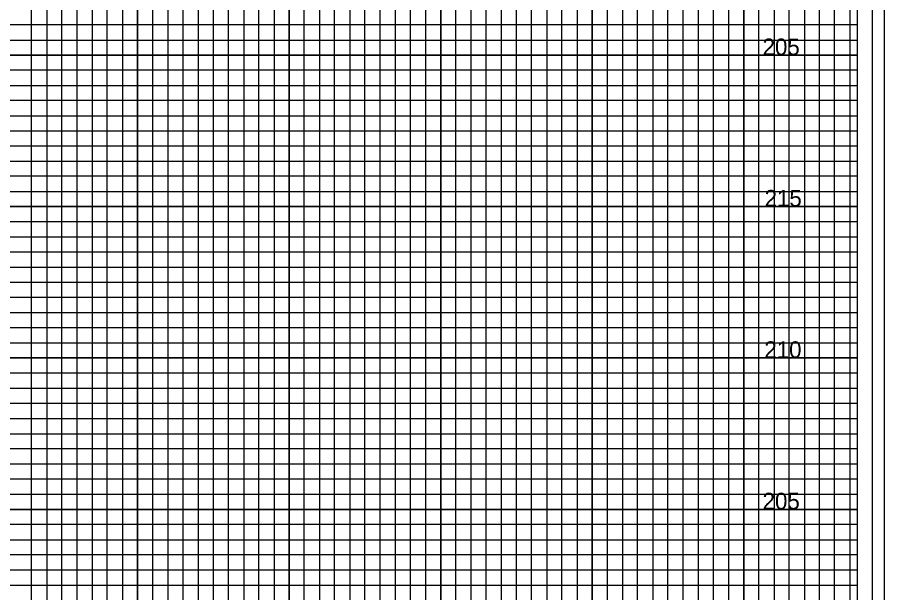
# Model space of a CAD drawing. Extents: x -4 to 103, y -2 to 209.
# Drawn here: x 74.78 to 103.4, y 32.25 to 51.25 of the extents above; entities that cross this region are included whole.
import ezdxf

# ---------------------------------------------------------------- set-up
doc = ezdxf.new("R2010")
doc.units = 0
for name, color, linetype in [('Old_Level_10', 7, 'Continuous'), ('Old_Level_17', 7, 'Continuous'), ('Old_Level_5', 7, 'Continuous'), ('Old_Level_6', 7, 'Continuous'), ('Old_Level_8', 7, 'Continuous'), ('Prop Dimension', 7, 'Continuous'), ('Typical Curb CELL', 7, 'Continuous')]:
    doc.layers.add(name, color=color, linetype=linetype)

msp = doc.modelspace()

# ---------------------------------------------------------------- linework, layer by layer
at = {"layer": 'Old_Level_10'}
for p, q in [((91.25, 0), (91.25, 63.425)), ((93.75, 0), (93.75, 63.425)), ((96.25, 0), (96.25, 63.425)), ((98.75, 0), (98.75, 63.425)), ((101.25, 0), (101.25, 63.425)), ((76.25, 0), (76.25, 62)), ((78.75, 0), (78.75, 62)), ((81.25, 0), (81.25, 62)), ((83.75, 0), (83.75, 62)), ((86.25, 0), (86.25, 62)), ((88.75, 0), (88.75, 62)), ((0, 50), (102.5, 50)), ((0, 47.5), (102.5, 47.5)), ((0, 45), (102.5, 45)), ((0, 42.5), (102.5, 42.5)), ((0, 40), (102.5, 40)), ((0, 37.5), (102.5, 37.5)), ((0, 35), (102.5, 35)), ((0, 32.5), (102.5, 32.5))]:
    msp.add_line(p, q, dxfattribs=at)
at = {"layer": 'Old_Level_17'}
for points in [[(90.25, 0), (90.25, 63.425), (90.75, 63.425), (90.75, 0)], [(91.75, 0), (91.75, 63.425), (92.25, 63.425), (92.25, 0)], [(92.75, 0), (92.75, 63.425), (93.25, 63.425), (93.25, 0)], [(94.25, 0), (94.25, 63.425), (94.75, 63.425), (94.75, 0)], [(95.25, 0), (95.25, 63.425), (95.75, 63.425), (95.75, 0)], [(96.75, 0), (96.75, 63.425), (97.25, 63.425), (97.25, 0)], [(97.75, 0), (97.75, 63.425), (98.25, 63.425), (98.25, 0)], [(99.25, 0), (99.25, 63.425), (99.75, 63.425), (99.75, 0)], [(100.25, 0), (100.25, 63.425)], [(100.25, 63.425), (100.75, 63.425), (100.75, 0), (101.75, 0), (101.75, 63.425), (102.25, 63.425), (102.25, 0)], [(75.25, 0), (75.25, 62), (75.75, 62), (75.75, 0)], [(76.75, 0), (76.75, 62), (77.25, 62), (77.25, 0)], [(77.75, 0), (77.75, 62), (78.25, 62), (78.25, 0)], [(79.25, 0), (79.25, 62), (79.75, 62), (79.75, 0)], [(80.25, 0), (80.25, 62), (80.75, 62), (80.75, 0)], [(81.75, 0), (81.75, 62), (82.25, 62), (82.25, 0)], [(82.75, 0), (82.75, 62), (83.25, 62), (83.25, 0)], [(84.25, 0), (84.25, 62), (84.75, 62), (84.75, 0)], [(85.25, 0), (85.25, 62), (85.75, 62), (85.75, 0)], [(86.75, 0), (86.75, 62), (87.25, 62), (87.25, 0)], [(87.75, 0), (87.75, 62), (88.25, 62), (88.25, 0)], [(89.25, 0), (89.25, 62), (89.75, 62), (89.75, 0)], [(0, 50.5), (102.5, 50.5), (102.5, 51), (0, 51)], [(0, 49), (102.5, 49), (102.5, 49.5), (0, 49.5)], [(0, 48), (102.5, 48), (102.5, 48.5), (0, 48.5)], [(0, 46.5), (102.5, 46.5), (102.5, 47), (0, 47)], [(0, 45.5), (102.5, 45.5), (102.5, 46), (0, 46)], [(0, 44), (102.5, 44), (102.5, 44.5), (0, 44.5)], [(0, 43), (102.5, 43), (102.5, 43.5), (0, 43.5)], [(0, 41.5), (102.5, 41.5), (102.5, 42), (0, 42)], [(0, 40.5), (102.5, 40.5), (102.5, 41), (0, 41)], [(0, 39), (102.5, 39), (102.5, 39.5), (0, 39.5)], [(0, 38), (102.5, 38), (102.5, 38.5), (0, 38.5)], [(0, 36.5), (102.5, 36.5), (102.5, 37), (0, 37)], [(0, 35.5), (102.5, 35.5), (102.5, 36), (0, 36)], [(0, 34), (102.5, 34), (102.5, 34.5), (0, 34.5)], [(0, 33), (102.5, 33), (102.5, 33.5), (0, 33.5)]]:
    msp.add_lwpolyline(points, dxfattribs=at)
at = {"layer": 'Old_Level_5'}
msp.add_lwpolyline([(103.4, 67.4), (-3.5, 67.4), (-3.5, -2.425), (103.4, -2.425)], close=True, dxfattribs=at)
at = {"layer": 'Old_Level_6'}
msp.add_lwpolyline([(102.5, 65), (0, 65), (0, 0), (102.5, 0)], close=True, dxfattribs=at)
at = {"layer": 'Old_Level_8'}
for points in [[(91.25, 0), (91.25, 63.425), (93.75, 63.425), (93.75, 0)], [(96.25, 0), (96.25, 63.425), (98.75, 63.425), (98.75, 0)], [(101.25, 0), (101.25, 63.425)], [(76.25, 0), (76.25, 62), (78.75, 62), (78.75, 0)], [(81.25, 0), (81.25, 62), (83.75, 62), (83.75, 0)], [(86.25, 0), (86.25, 62), (88.75, 62), (88.75, 0)], [(0, 47.5), (102.5, 47.5), (102.5, 50), (0, 50)], [(0, 42.5), (102.5, 42.5), (102.5, 45), (0, 45)], [(0, 37.5), (102.5, 37.5), (102.5, 40), (0, 40)], [(0, 32.5), (102.5, 32.5), (102.5, 35), (0, 35)]]:
    msp.add_lwpolyline(points, dxfattribs=at)
at = {"layer": 'Typical Curb CELL'}
msp.add_lwpolyline([(103, 66), (-2.8, 66), (-2.8, -1), (103, -1)], close=True, dxfattribs=at)

# ---------------------------------------------------------------- texts
at = {"layer": 'Prop Dimension'}
for s, p in [('205', (99.3724, 50)), ('215', (99.4383, 45)), ('210', (99.4296, 40)), ('205', (99.3724, 35))]:
    msp.add_text(s, height=0.55, dxfattribs=at).set_placement(p)

doc.saveas('drawing.dxf')
